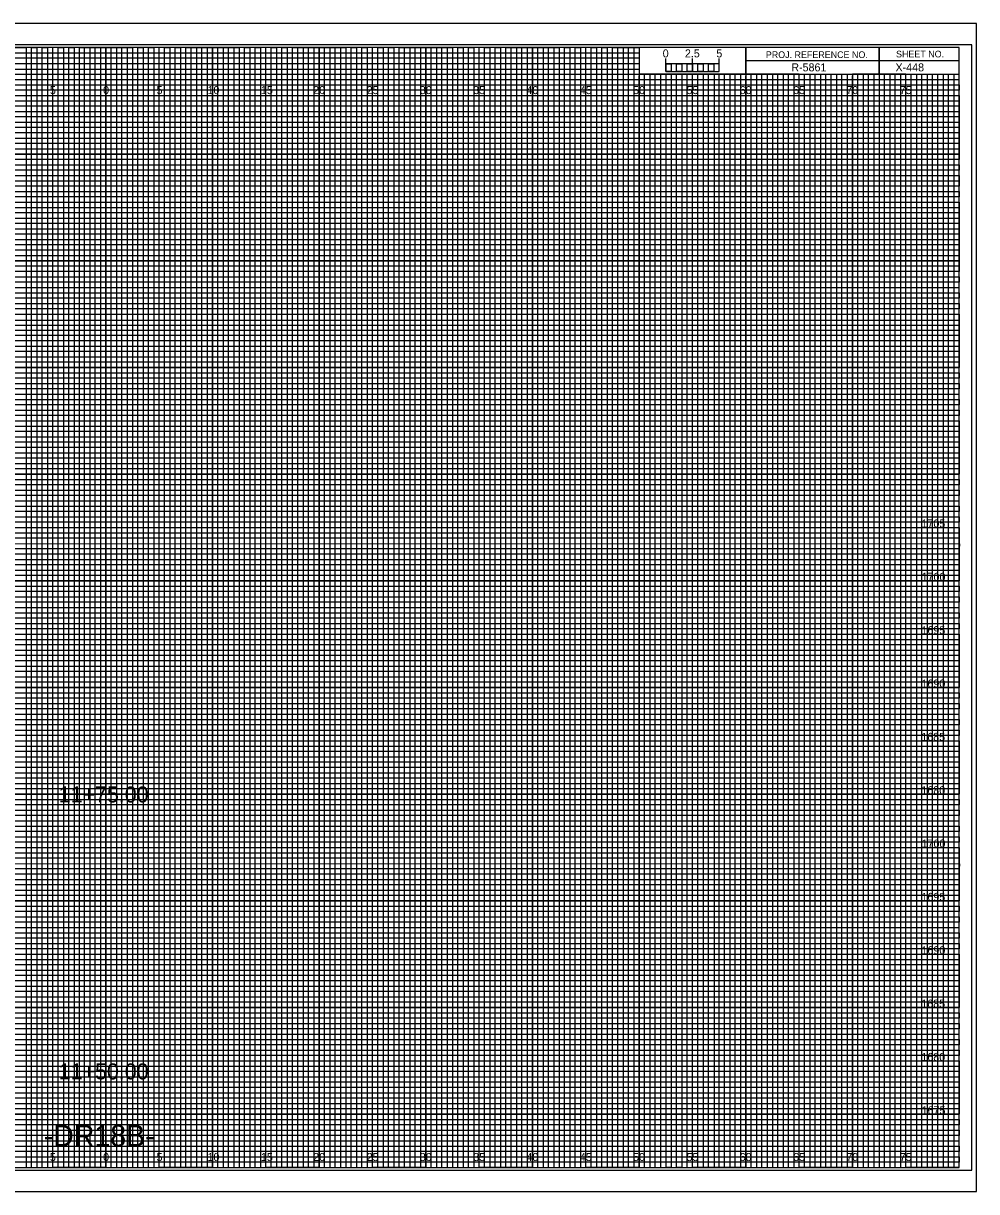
# Model space of a CAD drawing. Extents: x -7 to 162, y -2 to 217.
# Drawn here: x 72.2 to 161.7, y 107.7 to 217.2 of the extents above; entities that cross this region are included whole.
import ezdxf

# ---------------------------------------------------------------- set-up
doc = ezdxf.new("R2010")
doc.units = 0
for name, color, linetype in [('Prop Horizontal Alignment', 7, 'Continuous'), ('Prop XS Alignment Label', 7, 'Continuous'), ('Prop XS Bar Scale Labels', 7, 'Continuous'), ('Prop XS Project Number', 7, 'Continuous'), ('Prop XS Sheet Number', 7, 'Continuous'), ('Raster_Level_0', 7, 'Continuous'), ('Scratch_Level_3', 7, 'Continuous'), ('Sheet Cross Section CELL', 7, 'Continuous'), ('Sheet Cross Section Grid Major CELL', 7, 'Continuous'), ('Sheet Cross Section Grid Middle CELL', 7, 'Continuous'), ('Sheet Cross Section Grid Minor 1 CELL', 7, 'Continuous'), ('Sheet Cross Section Grid Minor 2 CELL', 7, 'Continuous'), ('Sheet Cross Section Scale CELL', 7, 'Continuous'), ('Sheet Cutting Line CELL', 7, 'Continuous'), ('Sheet DOT Grid CELL', 7, 'Continuous'), ('Sheet Plot Border Inside CELL', 7, 'Continuous'), ('Sheet Plot Border Outside CELL', 7, 'Continuous')]:
    doc.layers.add(name, color=color, linetype=linetype)

msp = doc.modelspace()

# ---------------------------------------------------------------- linework, layer by layer
at = {"layer": 'Sheet Cross Section CELL'}
for p, q in [((152.5, 215), (152.5, 212.5)), ((152.5, 212.5), (152.5, 215)), ((160, 213.75), (140, 213.75)), ((140, 213.75), (140, 212.5)), ((140, 212.5), (160, 212.5))]:
    msp.add_line(p, q, dxfattribs=at)
for points in [[(160, 215), (0, 215), (0, 110), (160, 110)], [(140, 215), (130, 215), (130, 212.52), (140, 212.52)], [(160, 215), (140, 215), (140, 212.5), (160, 212.5)]]:
    msp.add_lwpolyline(points, close=True, dxfattribs=at)
at = {"layer": 'Sheet Cross Section Grid Major CELL'}
for p, q in [((75, 215), (70, 215)), ((75, 110), (75, 215)), ((85, 215), (80, 215)), ((80, 215), (80, 110)), ((85, 110), (85, 215)), ((95, 215), (90, 215)), ((90, 215), (90, 110)), ((95, 110), (95, 215)), ((105, 215), (100, 215)), ((100, 215), (100, 110)), ((105, 110), (105, 215)), ((115, 215), (110, 215)), ((110, 215), (110, 110)), ((115, 110), (115, 215)), ((125, 215), (120, 215)), ((120, 215), (120, 110)), ((125, 110), (125, 215)), ((130, 215), (130, 110)), ((135, 110), (135, 212.5)), ((145, 212.5), (140, 212.5)), ((140, 212.5), (140, 110)), ((145, 110), (145, 212.5)), ((155, 212.5), (150, 212.5)), ((150, 212.5), (150, 110)), ((155, 110), (155, 212.5)), ((80, 110), (75, 110)), ((90, 110), (85, 110)), ((100, 110), (95, 110)), ((110, 110), (105, 110)), ((120, 110), (115, 110)), ((130, 110), (125, 110)), ((140, 110), (135, 110)), ((150, 110), (145, 110)), ((160, 110), (155, 110)), ((160, 110), (160, 110))]:
    msp.add_line(p, q, dxfattribs=at)
for points in [[(0, 210), (160, 210), (160, 205), (0, 205)], [(0, 200), (160, 200), (160, 195), (0, 195)], [(0, 190), (160, 190), (160, 185), (0, 185)], [(0, 180), (160, 180), (160, 175), (0, 175)], [(0, 170), (160, 170), (160, 165), (0, 165)], [(0, 160), (160, 160), (160, 155), (0, 155)], [(0, 150), (160, 150), (160, 145), (0, 145)], [(0, 140), (160, 140), (160, 135), (0, 135)], [(0, 130), (160, 130), (160, 125), (0, 125)], [(0, 120), (160, 120), (160, 115), (0, 115)]]:
    msp.add_lwpolyline(points, dxfattribs=at)
at = {"layer": 'Sheet Cross Section Grid Middle CELL'}
for points in [[(67.5, 215), (72.5, 215), (72.5, 110), (77.5, 110), (77.5, 215), (82.5, 215), (82.5, 110), (87.5, 110), (87.5, 215), (92.5, 215), (92.5, 110), (97.5, 110), (97.5, 215), (102.5, 215), (102.5, 110), (107.5, 110), (107.5, 215), (112.5, 215), (112.5, 110), (117.5, 110), (117.5, 215), (122.5, 215), (122.5, 110), (127.5, 110), (127.5, 215), (129.97, 215), (130, 215), (130, 212.5), (132.5, 212.5), (132.5, 110), (137.5, 110), (137.5, 212.5), (142.5, 212.5), (142.5, 110), (147.5, 110), (147.5, 212.5), (152.5, 212.5), (152.5, 110), (157.5, 110), (157.5, 212.5)], [(0, 212.5), (137.5, 212.5)], [(0, 202.5), (160, 202.5), (160, 207.5), (0, 207.5)], [(0, 192.5), (160, 192.5), (160, 197.5), (0, 197.5)], [(0, 182.5), (160, 182.5), (160, 187.5), (0, 187.5)], [(0, 172.5), (160, 172.5), (160, 177.5), (0, 177.5)], [(0, 162.5), (160, 162.5), (160, 167.5), (0, 167.5)], [(0, 152.5), (160, 152.5), (160, 157.5), (0, 157.5)], [(0, 142.5), (160, 142.5), (160, 147.5), (0, 147.5)], [(0, 132.5), (160, 132.5), (160, 137.5), (0, 137.5)], [(0, 122.5), (160, 122.5), (160, 127.5), (0, 127.5)], [(0, 112.5), (160, 112.5), (160, 117.5), (0, 117.5)]]:
    msp.add_lwpolyline(points, dxfattribs=at)
at = {"layer": 'Sheet Cross Section Grid Minor 1 CELL'}
for p, q in [((0, 214.5), (130, 214.5)), ((130, 213.99), (0, 213.99)), ((130, 214.5), (130, 213.99)), ((0, 213.5), (130, 213.5)), ((130, 212.94), (0, 212.94)), ((130, 213.5), (130, 212.94)), ((0, 212), (160, 212))]:
    msp.add_line(p, q, dxfattribs=at)
for points in [[(0, 211.5), (135, 211.5), (160, 211.5), (160, 211), (0, 211)], [(0, 210.5), (160, 210.5), (160, 209.5), (0, 209.5)], [(0, 209), (160, 209), (160, 208.5), (0, 208.49)], [(0, 208), (160, 208), (160, 207), (0, 207)], [(0, 206.5), (160, 206.5), (160, 206), (0, 206)], [(0, 205.5), (160, 205.5), (160, 204.5), (0, 204.5)], [(0, 204), (160, 204), (160, 203.5), (0, 203.5)], [(0, 203), (160, 203), (160, 202), (0, 202)], [(0, 201.5), (160, 201.5), (160, 201), (0, 201)], [(0, 200.5), (160, 200.5), (160, 199.5), (0, 199.5)], [(0, 199), (160, 199), (160, 198.5), (0, 198.5)], [(0, 198), (160, 198), (160, 196.97), (160, 196.5), (160, 196), (0, 196)], [(0, 197), (160, 197), (160, 196.5), (0, 196.5)], [(0, 195.5), (160, 195.5), (160, 194.5), (0, 194.52)], [(0, 194.52), (160, 194.5), (160, 194), (0, 194)], [(0, 193.5), (160, 193.5), (160, 193), (0, 193)], [(0, 192), (160, 192), (160, 191.5), (0, 191.5)], [(0, 191), (160, 191), (160, 190.5), (0, 190.5)], [(-0.04, 189.44), (160, 189.44), (160, 188.94), (-0.04, 188.94)], [(0, 188.5), (160, 188.5), (160, 188), (0, 188)], [(0, 187), (160, 187), (160, 186.5), (0, 186.5)], [(0, 186), (160, 186), (160, 185.5), (0, 185.5)], [(0, 184.5), (160, 184.5), (160, 184), (0, 184)], [(0, 183.5), (160, 183.5), (160, 183), (0, 183)], [(0, 182), (160, 182), (160, 181.5), (0, 181.5)], [(0, 181), (160, 181), (160, 180.5), (0, 180.5)], [(0, 179.5), (160, 179.5), (160, 178.99), (0, 179)], [(0, 178.5), (160, 178.5), (160, 178), (0, 178)], [(0, 177), (160, 177), (160, 176.5), (0, 176.5)], [(0, 176), (160, 176), (160, 175.5), (0, 175.5)], [(0, 174.5), (160, 174.5), (160, 174), (0, 174)], [(0, 173.5), (160, 173.5), (160, 173), (0, 173)], [(0, 172), (160, 172), (160, 171.5), (0, 171.5)], [(0, 171), (160, 171), (160, 170.5), (0, 170.5)], [(0, 169.5), (160, 169.5), (160, 169), (0, 169)], [(0, 168.5), (160.03, 168.46), (160, 168), (0, 168)], [(0, 167), (160, 167), (160, 166.5), (0, 166.5)], [(0, 166), (160, 166), (160, 165.5), (0, 165.5)], [(0, 164.5), (160, 164.5), (160, 164), (0, 164)], [(0, 163.5), (160, 163.5), (160, 163), (0, 163)], [(0, 162), (160, 162), (160, 161.5), (0, 161.5)], [(0, 161), (160, 161), (160, 160.5), (0, 160.5)], [(0, 159.5), (160, 159.5), (160, 159), (0, 159)], [(0, 158.5), (160, 158.5), (160, 158), (0, 158)], [(0, 157), (160, 157), (160, 156.5), (0, 156.5)], [(0, 156), (160, 156), (160, 155.5), (0, 155.5)], [(0, 154.5), (160, 154.5), (160, 154), (0, 154)], [(0, 153.5), (160, 153.5), (160, 153), (0, 153)], [(0, 152), (160, 152), (160, 151.5), (0, 151.5)], [(0, 151), (160, 151), (160, 150.5), (0, 150.5)], [(0, 149.5), (160, 149.5), (160, 148.99), (0, 149)], [(0, 148.5), (160, 148.5), (160, 148), (0, 148)], [(0, 147), (160, 147), (160, 146.5), (0, 146.5)], [(0, 146), (160, 146), (160, 145.5), (0, 145.5)], [(0, 144.5), (160, 144.5), (160, 144), (0, 144)], [(0, 143.5), (160, 143.5), (160, 143), (0, 143)], [(0, 142), (160, 142), (160, 141.5), (0, 141.5)], [(0, 141), (160, 141), (160, 140.5), (0, 140.5)], [(0, 139.5), (160, 139.5), (160, 139), (0, 139)], [(0, 138.5), (160.03, 138.46), (160, 138), (0, 138)], [(0, 137), (160, 137), (160, 136.5), (0, 136.5)], [(0, 136), (160, 136), (160, 135.5), (0, 135.5)], [(0, 134.5), (160, 134.5), (160, 134), (0, 134)], [(0, 133.5), (160, 133.5), (160, 133), (0, 133)], [(0, 132), (160, 132), (160, 131.5), (0, 131.5)], [(0, 131), (160, 131), (160, 130.5), (0, 130.5)], [(0, 129.5), (160, 129.5), (160, 129), (0, 129)], [(0, 128.5), (160, 128.5), (160, 128), (0, 128)], [(0, 127), (160, 127), (160, 126.5), (0, 126.5)], [(0, 126), (160, 126), (160, 125.5), (0, 125.5)], [(0, 124.5), (160, 124.5), (160, 124), (0, 124)], [(0, 123.5), (160, 123.5), (160, 123), (0, 123)], [(0, 122), (160, 122), (160, 121.5), (0, 121.5)], [(0, 121), (160, 121), (160, 120.5), (0, 120.5)], [(0, 119.5), (160, 119.5), (160, 119), (0, 119)], [(0, 118.5), (160, 118.5), (160, 118), (0, 118)], [(0, 117), (160, 117), (160, 116.5), (0, 116.5)], [(0, 116), (160, 116), (160, 115.5), (0, 115.5)], [(0, 114.5), (160, 114.5), (160, 114), (0, 114)], [(0, 113.5), (160, 113.5), (160, 113), (0, 113)], [(0, 112), (160, 112), (160, 111.5), (0, 111.5)], [(0, 111), (160, 111), (160, 110.5), (0, 110.5)]]:
    msp.add_lwpolyline(points, dxfattribs=at)
at = {"layer": 'Sheet Cross Section Grid Minor 2 CELL'}
for p, q in [((133.5, 212.5), (133, 212.5)), ((133, 212.5), (133, 110)), ((133.5, 110), (133.5, 212.5)), ((134.5, 212.5), (134, 212.5)), ((134, 212.5), (134, 110)), ((134.5, 110), (134.5, 212.5)), ((133, 110), (132.5, 110)), ((134, 110), (133.5, 110))]:
    msp.add_line(p, q, dxfattribs=at)
for points in [[(72.5, 110), (73, 110), (73, 215), (73.5, 215), (73.5, 110)], [(73.5, 110), (74, 110), (74, 215), (74.5, 215), (74.5, 110)], [(75, 110), (75.5, 110), (75.5, 215), (76, 215), (76, 110)], [(76, 110), (76.5, 110), (76.5, 215), (77, 215), (77, 110)], [(77.5, 110), (78, 110), (78, 215), (78.5, 215), (78.5, 110)], [(78.5, 110), (79, 110), (79, 215), (79.5, 215), (79.5, 110)], [(80, 110), (80.5, 110), (80.5, 215), (81, 215), (81, 110)], [(81, 110), (81.5, 110), (81.5, 215), (82, 215), (82, 110)], [(82.5, 110), (83, 110), (83, 215), (83.5, 215), (83.5, 110)], [(83.5, 110), (84, 110), (84, 215), (84.5, 215), (84.5, 110)], [(85, 110), (85.5, 110), (85.5, 215), (86, 215), (86, 110)], [(86, 110), (86.5, 110), (86.5, 215), (87, 215), (87, 110)], [(87.5, 110), (88, 110), (88, 215), (88.5, 215), (88.5, 110)], [(88.5, 110), (89, 110), (89, 215), (89.5, 215), (89.5, 110)], [(90, 110), (90.5, 110), (90.5, 215), (91, 215), (91, 110)], [(91, 110), (91.5, 110), (91.5, 215), (92, 215), (92, 110)], [(92.5, 110), (93, 110), (93, 215), (93.5, 215), (93.5, 110)], [(93.5, 110), (94, 110), (94, 215), (94.5, 215), (94.5, 110)], [(95, 110), (95.5, 110), (95.5, 215), (96, 215), (96, 110)], [(96, 110), (96.5, 110), (96.5, 215), (97, 215), (97, 110)], [(97.5, 110), (98, 110), (98, 215), (98.5, 215), (98.5, 110)], [(98.5, 110), (99, 110), (99, 215), (99.5, 215), (99.5, 110)], [(100, 110), (100.5, 110), (100.5, 215), (101, 215), (101, 110)], [(101, 110), (101.5, 110), (101.5, 215), (102, 215), (102, 110)], [(102.5, 110), (103, 110), (103, 215), (103.5, 215), (103.5, 110)], [(103.5, 110), (104, 110), (104, 215), (104.5, 215), (104.5, 110)], [(105, 110), (105.5, 110), (105.5, 215), (106, 215), (106, 110)], [(106, 110), (106.5, 110), (106.5, 215), (107, 215), (107, 110)], [(107.5, 110), (108, 110), (108, 215), (108.5, 215), (108.5, 110)], [(108.5, 110), (109, 110), (109, 215), (109.5, 215), (109.5, 110)], [(110, 110), (110.5, 110), (110.5, 215), (111, 215), (111, 110)], [(111, 110), (111.5, 110), (111.5, 215), (112, 215), (112, 110)], [(112.5, 110), (113, 110), (113, 215), (113.5, 215), (113.5, 110)], [(113.5, 110), (114, 110), (114, 215), (114.5, 215), (114.5, 110)], [(115, 110), (115.5, 110), (115.5, 215), (116, 215), (116, 110)], [(116, 110), (116.5, 110), (116.5, 215), (117, 215), (117, 110)], [(117.5, 110), (118, 110), (118, 215), (118.5, 215), (118.5, 110)], [(118.5, 110), (119, 110), (119, 215), (119.5, 215), (119.5, 110)], [(120, 110), (120.5, 110), (120.5, 215), (121, 215), (121, 110)], [(121, 110), (121.5, 110), (121.5, 215), (122, 215), (122, 110)], [(122.5, 110), (123, 110), (123, 215), (123.5, 215), (123.5, 110)], [(123.5, 110), (124, 110), (124, 215), (124.5, 215), (124.5, 110)], [(125, 110), (125.5, 110), (125.5, 215), (126, 215), (126, 110)], [(126, 110), (126.5, 110), (126.5, 215), (127, 215), (127, 110)], [(127.5, 110), (128, 110), (128, 215), (128.5, 215), (128.5, 110)], [(128.5, 110), (129, 110), (129, 215), (129.5, 215), (129.5, 110)], [(130, 110), (130.5, 110), (130.5, 212.5), (131.01, 212.5), (131.01, 110)], [(131, 110), (131.5, 110), (131.5, 212.5), (132, 212.5), (132, 110)], [(135, 110), (135.49, 110), (135.49, 212.5), (136, 212.5), (136, 110)], [(136, 110), (136.5, 110), (136.5, 212.5), (137.03, 212.5), (137.03, 110)], [(137.5, 110), (138, 110), (138, 212.5), (138.5, 212.5), (138.5, 110)], [(138.5, 110), (139, 110), (139, 212.5), (139.5, 212.5), (139.5, 110)], [(140, 110), (140.5, 110), (140.5, 212.5), (141, 212.5), (141, 110)], [(141, 110), (141.5, 110), (141.5, 212.5), (142, 212.5), (142, 110)], [(142.5, 110), (143, 110), (143, 212.5), (143.5, 212.5), (143.5, 110)], [(143.5, 110), (144, 110), (144, 212.5), (144.5, 212.5), (144.5, 110)], [(145, 110), (145.5, 110), (145.5, 212.5), (146, 212.5), (146, 110)], [(146, 110), (146.5, 110), (146.5, 212.5), (147, 212.5), (147, 110)], [(147.5, 110), (148, 110), (148, 212.5), (148.5, 212.5), (148.5, 110)], [(148.5, 110), (149, 110), (149, 212.5), (149.5, 212.5), (149.5, 110)], [(150, 110), (150.5, 110), (150.5, 212.5), (151, 212.5), (151, 110)], [(151, 110), (151.5, 110), (151.5, 212.5), (152, 212.5), (152, 110)], [(152.5, 110), (153, 110), (153, 212.5), (153.5, 212.5), (153.5, 110)], [(153.5, 110), (154, 110), (154, 212.5), (154.5, 212.5), (154.5, 110)], [(155, 110), (155.5, 110), (155.5, 212.5), (156, 212.5), (156, 110)], [(156, 110), (156.5, 110), (156.5, 212.5), (157, 212.5), (157, 110)], [(157.5, 110), (158, 110), (158, 212.5), (158.5, 212.5), (158.5, 110)], [(158.5, 110), (159, 110), (159, 212.5), (159.5, 212.5), (159.5, 110)]]:
    msp.add_lwpolyline(points, dxfattribs=at)
at = {"layer": 'Sheet Cross Section Scale CELL'}
for p, q in [((132.5, 212.75), (132.5, 213.95)), ((132.5, 213.45), (132.5, 213.95)), ((135, 212.75), (135, 213.95)), ((137.5, 212.75), (137.5, 213.95)), ((137.5, 213.45), (137.5, 213.95))]:
    msp.add_line(p, q, dxfattribs=at)
for points in [[(137.5, 213.45), (132.5, 213.45), (132.5, 212.75), (137.5, 212.75)], [(132.5, 213.45), (133, 213.45), (133, 212.75), (132.5, 212.75)], [(133.5, 213.45), (134, 213.45), (134, 212.75), (133.5, 212.75)], [(134.5, 213.45), (135, 213.45), (135, 212.75), (134.5, 212.75)], [(135.5, 213.45), (136, 213.45), (136, 212.75), (135.5, 212.75)], [(136.5, 213.45), (137, 213.45), (137, 212.75), (136.5, 212.75)]]:
    msp.add_lwpolyline(points, close=True, dxfattribs=at)
at = {"layer": 'Sheet Cutting Line CELL'}
for p, q in [((161.65, 217.25), (-6.7, 217.25)), ((-6.7, 107.75), (161.65, 107.75))]:
    msp.add_line(p, q, dxfattribs=at)
at = {"layer": 'Sheet DOT Grid CELL'}
for p, q in [((75, 110), (75, 215)), ((80, 110), (80, 215)), ((85, 110), (85, 215)), ((90, 110), (90, 215)), ((95, 110), (95, 215)), ((100, 110), (100, 215)), ((105, 110), (105, 215)), ((110, 110), (110, 215)), ((115, 110), (115, 215)), ((120, 110), (120, 215)), ((125, 110), (125, 215)), ((130, 110), (130, 212.34)), ((135, 110), (135, 212.34)), ((140, 110), (140, 212.34)), ((145, 110), (145, 212.34)), ((150, 110), (150, 212.34)), ((155, 110), (155, 212.34)), ((0, 210), (160, 210)), ((0, 205), (160, 205)), ((0, 200), (160, 200)), ((0, 195), (160, 195)), ((0, 190), (160, 190)), ((0, 185), (160, 185)), ((0, 180), (160, 180)), ((0, 175), (160, 175)), ((0, 170), (160, 170)), ((0, 165), (160, 165)), ((0, 160), (160, 160)), ((0, 155), (160, 155)), ((0, 150), (160, 150)), ((0, 145), (160, 145)), ((0, 140), (160, 140)), ((0, 135), (160, 135)), ((0, 130), (160, 130)), ((0, 125), (160, 125)), ((0, 120), (160, 120)), ((0, 115), (160, 115))]:
    msp.add_line(p, q, dxfattribs=at)
at = {"layer": 'Sheet Plot Border Inside CELL'}
msp.add_lwpolyline([(-5.4, 109.75), (161.2, 109.75), (161.2, 215.25), (-5.4, 215.25)], close=True, dxfattribs=at)
at = {"layer": 'Sheet Plot Border Outside CELL'}
msp.add_lwpolyline([(-6.7, 107.75), (161.65, 107.75), (161.65, 217.25), (-6.7, 217.25)], close=True, dxfattribs=at)

# ---------------------------------------------------------------- texts
at = {"layer": 'Prop Horizontal Alignment'}
for s, p in [('11+75.00', (75.57, 144.23)), ('11+50.00', (75.57, 118.27))]:
    msp.add_text(s, height=1.5, dxfattribs=at).set_placement(p)
at = {"layer": 'Prop XS Alignment Label'}
msp.add_text('-DR18B-', height=2, dxfattribs=at).set_placement((74.16, 112))
at = {"layer": 'Prop XS Bar Scale Labels'}
for s, p in [('2.5', (134.29, 214.06)), ('5', (137.24, 214.06))]:
    msp.add_text(s, height=0.75, dxfattribs=at).set_placement(p)
at = {"layer": 'Prop XS Project Number'}
msp.add_text('R-5861', height=0.75, dxfattribs=at).set_placement((144.27, 212.75))
at = {"layer": 'Prop XS Sheet Number'}
msp.add_text('X-448', height=0.75, dxfattribs=at).set_placement((154.04, 212.75))
at = {"layer": 'Raster_Level_0'}
for s, p in [('5', (74.74, 210.62)), ('0', (79.73, 210.62)), ('0', (79.73, 210.62)), ('5', (84.74, 210.62)), ('10', (89.52, 210.62)), ('15', (94.53, 210.62)), ('20', (99.43, 210.62)), ('25', (104.44, 210.62)), ('30', (109.43, 210.62)), ('35', (114.44, 210.62)), ('40', (119.43, 210.62)), ('45', (124.44, 210.62)), ('50', (129.43, 210.62)), ('55', (134.44, 210.62)), ('60', (139.43, 210.62)), ('65', (144.44, 210.62)), ('70', (149.43, 210.62)), ('75', (154.44, 210.62)), ('5', (74.74, 110.62)), ('0', (79.73, 110.62)), ('0', (79.73, 110.62)), ('5', (84.74, 110.62)), ('10', (89.52, 110.62)), ('15', (94.53, 110.62)), ('20', (99.43, 110.62)), ('25', (104.44, 110.62)), ('30', (109.43, 110.62)), ('35', (114.44, 110.62)), ('40', (119.43, 110.62)), ('45', (124.44, 110.62)), ('50', (129.43, 110.62)), ('55', (134.44, 110.62)), ('60', (139.43, 110.62)), ('65', (144.44, 110.62)), ('70', (149.43, 110.62)), ('75', (154.44, 110.62))]:
    msp.add_text(s, height=0.75, dxfattribs=at).set_placement(p)
at = {"layer": 'Scratch_Level_3'}
for s, p in [('1705', (156.48, 170)), ('1700', (156.49, 165)), ('1695', (156.48, 160)), ('1690', (156.48, 155)), ('1685', (156.46, 150)), ('1680', (156.47, 145)), ('1700', (156.49, 140)), ('1695', (156.48, 135)), ('1690', (156.48, 130)), ('1685', (156.46, 125)), ('1680', (156.47, 120)), ('1675', (156.49, 115))]:
    msp.add_text(s, height=0.75, dxfattribs=at).set_placement(p)
at = {"layer": 'Sheet Cross Section CELL'}
for s, p in [('PROJ. REFERENCE NO.', (141.88, 214)), ('SHEET NO.', (154.09, 214.06))]:
    msp.add_text(s, height=0.625, dxfattribs=at).set_placement(p)
at = {"layer": 'Sheet Cross Section Scale CELL'}
msp.add_text('0', height=0.75, dxfattribs=at).set_placement((132.21, 214.06))

doc.saveas('drawing.dxf')
